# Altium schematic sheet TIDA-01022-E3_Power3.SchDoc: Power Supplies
size 431 x 279 mm; Date: Not shown in title block; ApprovedBy: Not shown in title block; CheckedBy: Not shown in title block; Author: Not shown in title block; CompanyName: Not shown in title block; DrawnBy: Avinash N; Engineer: Not shown in title block; Organization: Not shown in title block; Address1: Not shown in title block; Address2: Not shown in title block; Address3: Not shown in title block; Address4: Not shown in title block; DocumentNumber: 1; Revision: Use project parameter SCH_Rev; SheetNumber: 23; SheetTotal: 26; PageSetup: Record=PageOptions¦CenterHorizontal=True¦CenterVertical=True¦PrintScale=1.00¦XCorrection=1.00¦YCorrection=1.00¦PrintKind=0¦BorderSize=5000000¦LeftOffset=0¦BottomOffset=0¦Orientation=2¦PaperLength=1000¦PaperWidth=1000¦Scale=100¦PaperSource=15¦PrintQuality=600¦MediaType=1¦DitherType=10¦PaperKind=Letter¦PrintScaleMode=1
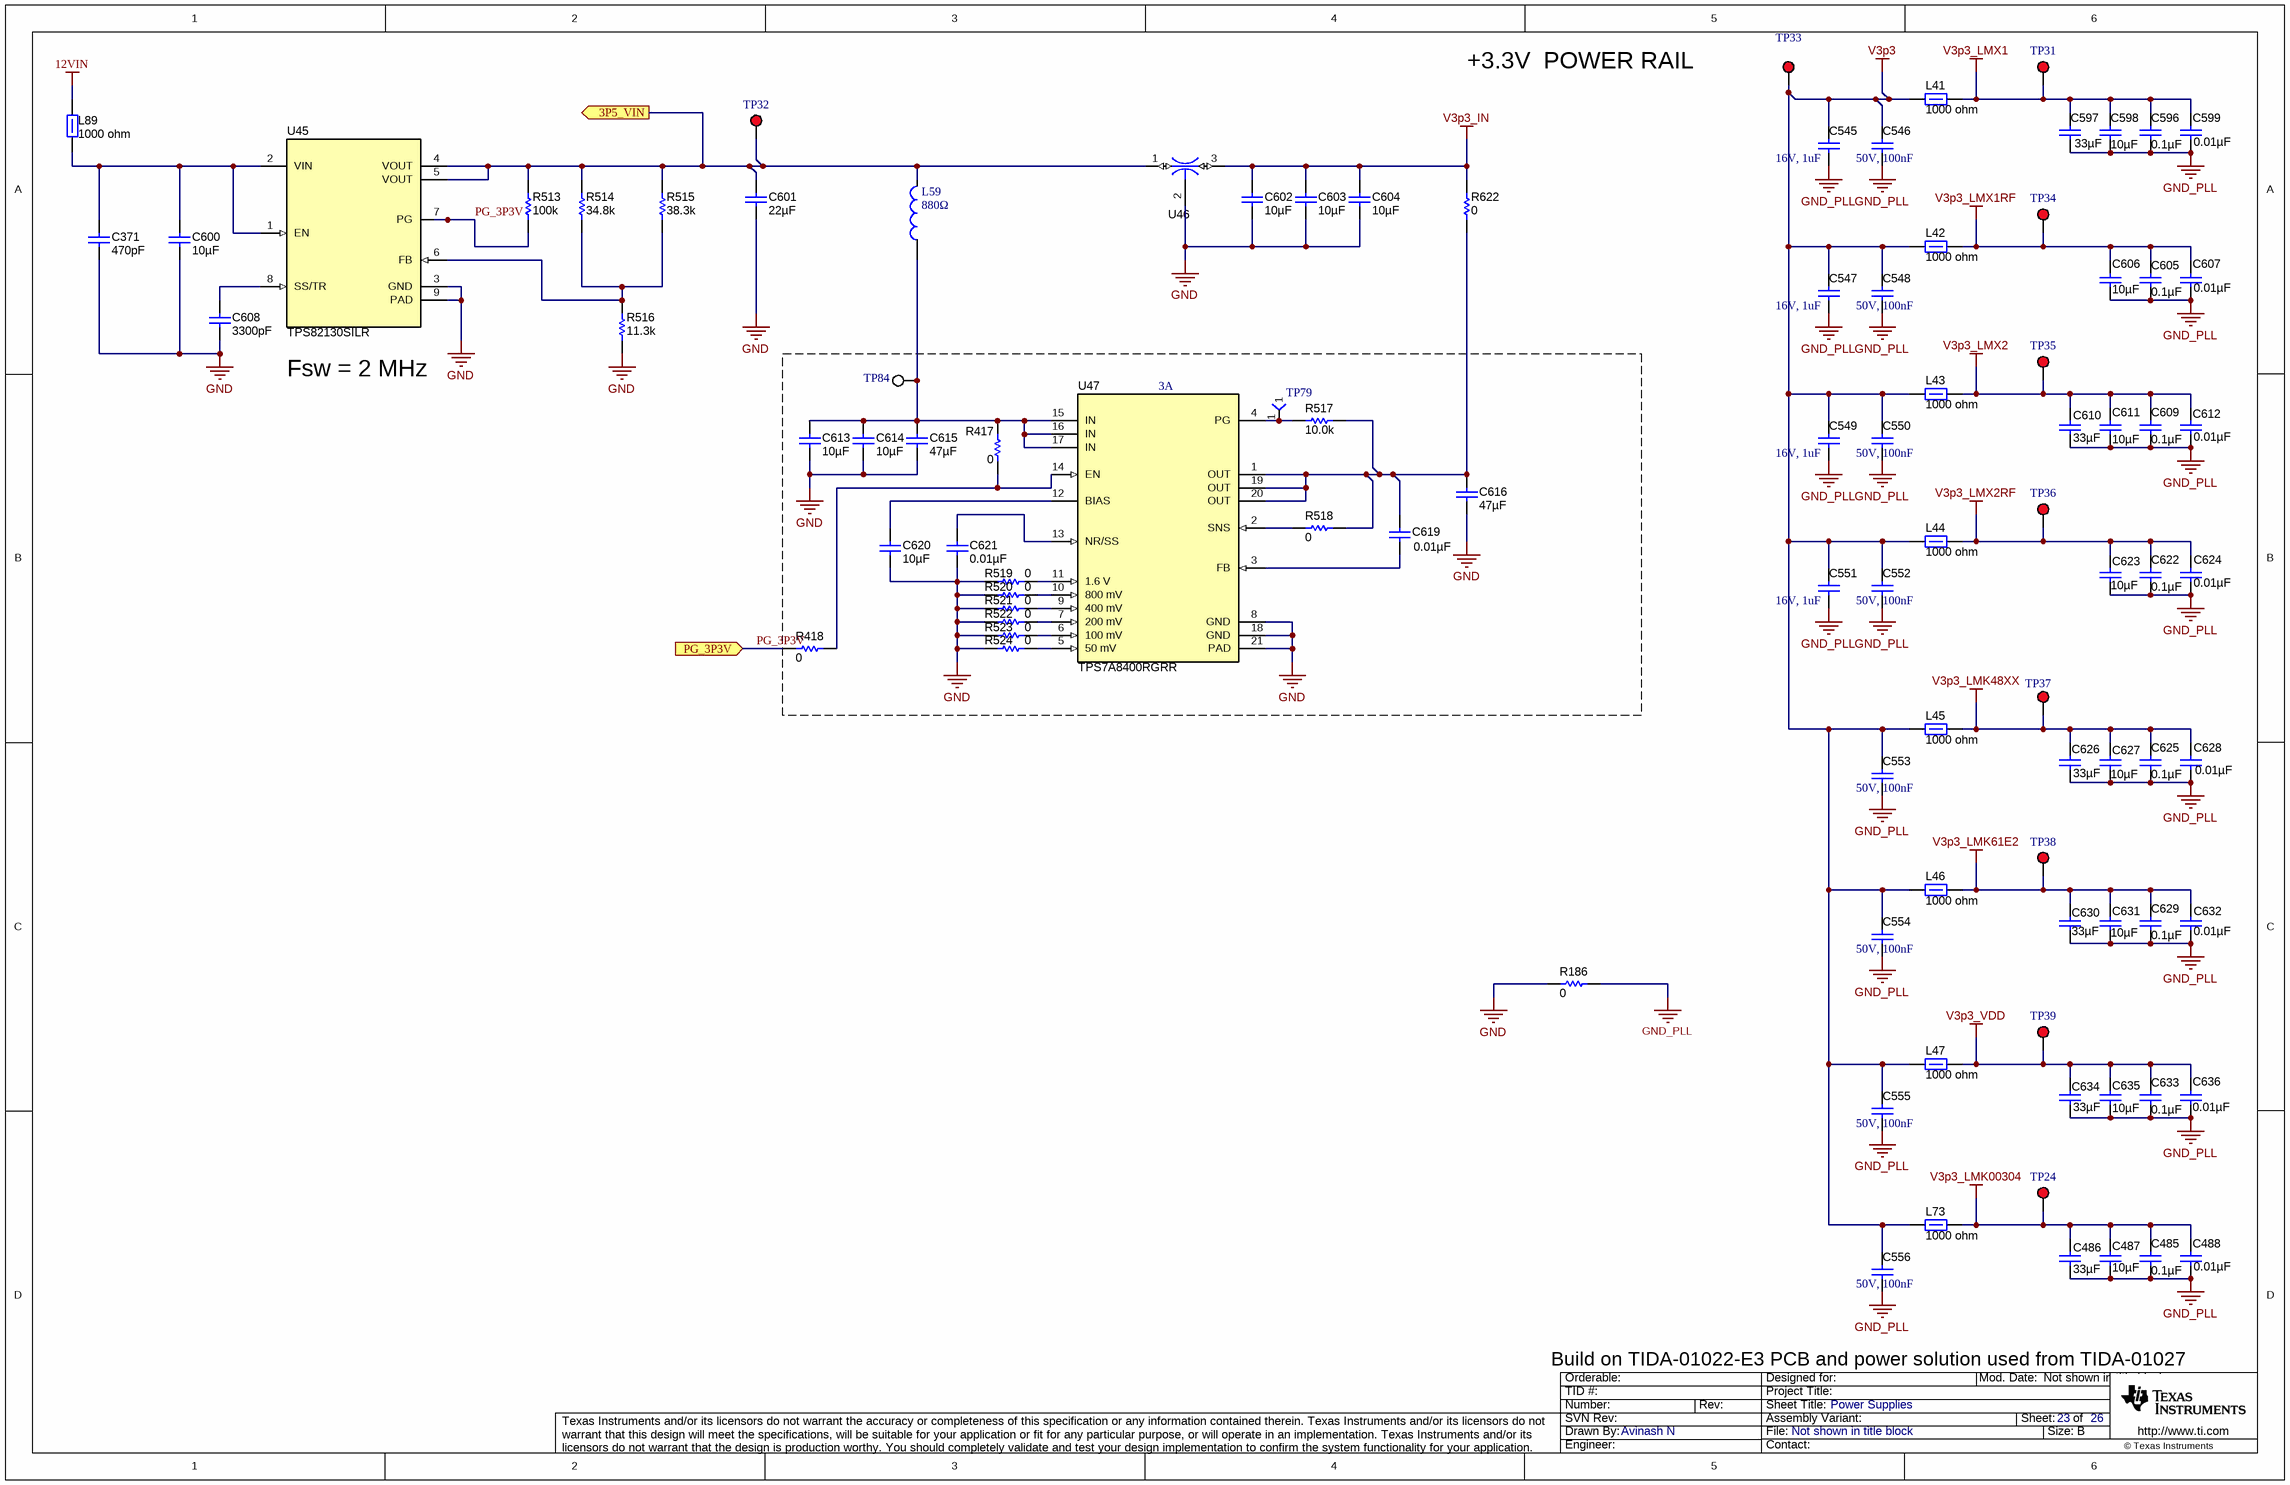
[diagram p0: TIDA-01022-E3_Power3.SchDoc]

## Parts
C371  ValueDisplayed: 470pF  [0402]  (hidden comment: GRM1555C1H471JA01D)
C485  ValueDisplayed: 0.1µF  [0603]  (hidden comment: CGA3E2X7R1H104K080AA)
C486  ValueDisplayed: 33µF  [1206_180]  (hidden comment: C3216X5R1E336M160AC)
C487  ValueDisplayed: 10µF  [1206_190]  (hidden comment: C3216X7R1E106M160AE)
C488  ValueDisplayed: 0.01µF  [0603]  (hidden comment: GCM188R71H103KA37D)
C545  16V, 1uF  [0603_1.6x0.8x0.8mm_Reflow Soldering]
C546  50V, 100nF  [0603_1.6x0.8x0.8mm_Reflow Soldering]
C547  16V, 1uF  [0603_1.6x0.8x0.8mm_Reflow Soldering]
C548  50V, 100nF  [0603_1.6x0.8x0.8mm_Reflow Soldering]
C549  16V, 1uF  [0603_1.6x0.8x0.8mm_Reflow Soldering]
C550  50V, 100nF  [0603_1.6x0.8x0.8mm_Reflow Soldering]
C551  16V, 1uF  [0603_1.6x0.8x0.8mm_Reflow Soldering]
C552  50V, 100nF  [0603_1.6x0.8x0.8mm_Reflow Soldering]
C553  50V, 100nF  [0603_1.6x0.8x0.8mm_Reflow Soldering]
C554  50V, 100nF  [0603_1.6x0.8x0.8mm_Reflow Soldering]
C555  50V, 100nF  [0603_1.6x0.8x0.8mm_Reflow Soldering]
C556  50V, 100nF  [0603_1.6x0.8x0.8mm_Reflow Soldering]
C596  ValueDisplayed: 0.1µF  [0603]  (hidden comment: CGA3E2X7R1H104K080AA)
C597  ValueDisplayed: 33µF  [1206_180]  (hidden comment: C3216X5R1E336M160AC)
C598  ValueDisplayed: 10µF  [1206_190]  (hidden comment: C3216X7R1E106M160AE)
C599  ValueDisplayed: 0.01µF  [0603]  (hidden comment: GCM188R71H103KA37D)
C600  ValueDisplayed: 10µF  [1206_190]  (hidden comment: C3216X7R1E106M160AE)
C601  ValueDisplayed: 22µF  [0805_HV]  (hidden comment: JMK212BJ226MG-T)
C602  ValueDisplayed: 10µF  [1206_190]  (hidden comment: C3216X7R1E106M160AE)
C603  ValueDisplayed: 10µF  [1206_190]  (hidden comment: C3216X7R1E106M160AE)
C604  ValueDisplayed: 10µF  [1206_190]  (hidden comment: C3216X7R1E106M160AE)
C605  ValueDisplayed: 0.1µF  [0603]  (hidden comment: CGA3E2X7R1H104K080AA)
C606  ValueDisplayed: 10µF  [1206_190]  (hidden comment: C3216X7R1E106M160AE)
C607  ValueDisplayed: 0.01µF  [0603]  (hidden comment: GCM188R71H103KA37D)
C608  ValueDisplayed: 3300pF  [0603]  (hidden comment: GRM1885C1H332JA01D)
C609  ValueDisplayed: 0.1µF  [0603]  (hidden comment: CGA3E2X7R1H104K080AA)
C610  ValueDisplayed: 33µF  [1206_180]  (hidden comment: C3216X5R1E336M160AC)
C611  ValueDisplayed: 10µF  [1206_190]  (hidden comment: C3216X7R1E106M160AE)
C612  ValueDisplayed: 0.01µF  [0603]  (hidden comment: GCM188R71H103KA37D)
C613  ValueDisplayed: 10µF  [0805_HV]  (hidden comment: GRM21BR61C106KE15L)
C614  ValueDisplayed: 10µF  [0805_HV]  (hidden comment: GRM21BR61C106KE15L)
C615  ValueDisplayed: 47µF  [0805_HV]  (hidden comment: GRM219R60G476ME44D)
C616  ValueDisplayed: 47µF  [0805_HV]  (hidden comment: GRM219R60G476ME44D)
C619  ValueDisplayed: 0.01µF  [0603]  (hidden comment: GRM188R71H103KA01D)
C620  ValueDisplayed: 10µF  [0805_HV]  (hidden comment: GRM21BR61C106KE15L)
C621  ValueDisplayed: 0.01µF  [0603]  (hidden comment: GRM188R71H103KA01D)
C622  ValueDisplayed: 0.1µF  [0603]  (hidden comment: CGA3E2X7R1H104K080AA)
C623  ValueDisplayed: 10µF  [1206_190]  (hidden comment: C3216X7R1E106M160AE)
C624  ValueDisplayed: 0.01µF  [0603]  (hidden comment: GCM188R71H103KA37D)
C625  ValueDisplayed: 0.1µF  [0603]  (hidden comment: CGA3E2X7R1H104K080AA)
C626  ValueDisplayed: 33µF  [1206_180]  (hidden comment: C3216X5R1E336M160AC)
C627  ValueDisplayed: 10µF  [1206_190]  (hidden comment: C3216X7R1E106M160AE)
C628  ValueDisplayed: 0.01µF  [0603]  (hidden comment: GCM188R71H103KA37D)
C629  ValueDisplayed: 0.1µF  [0603]  (hidden comment: CGA3E2X7R1H104K080AA)
C630  ValueDisplayed: 33µF  [1206_180]  (hidden comment: C3216X5R1E336M160AC)
C631  ValueDisplayed: 10µF  [1206_190]  (hidden comment: C3216X7R1E106M160AE)
C632  ValueDisplayed: 0.01µF  [0603]  (hidden comment: GCM188R71H103KA37D)
C633  ValueDisplayed: 0.1µF  [0603]  (hidden comment: CGA3E2X7R1H104K080AA)
C634  ValueDisplayed: 33µF  [1206_180]  (hidden comment: C3216X5R1E336M160AC)
C635  ValueDisplayed: 10µF  [1206_190]  (hidden comment: C3216X7R1E106M160AE)
C636  ValueDisplayed: 0.01µF  [0603]  (hidden comment: GCM188R71H103KA37D)
L41  ValueDisplayed: 1000 ohm  [1806_HighSpeed]  (hidden comment: BLM41PG102SN1L)
L42  ValueDisplayed: 1000 ohm  [1806_HighSpeed]  (hidden comment: BLM41PG102SN1L)
L43  ValueDisplayed: 1000 ohm  [1806_HighSpeed]  (hidden comment: BLM41PG102SN1L)
L44  ValueDisplayed: 1000 ohm  [1806_HighSpeed]  (hidden comment: BLM41PG102SN1L)
L45  ValueDisplayed: 1000 ohm  [1806_HighSpeed]  (hidden comment: BLM41PG102SN1L)
L46  ValueDisplayed: 1000 ohm  [1806_HighSpeed]  (hidden comment: BLM41PG102SN1L)
L47  ValueDisplayed: 1000 ohm  [1806_HighSpeed]  (hidden comment: BLM41PG102SN1L)
L59  880Ω  [WE-CBF_1812_High Current]
L73  ValueDisplayed: 1000 ohm  [1806_HighSpeed]  (hidden comment: BLM41PG102SN1L)
L89  ValueDisplayed: 1000 ohm  [1806_HighSpeed]  (hidden comment: BLM41PG102SN1L)
R186  ValueDisplayed: 0  [1206]  (hidden comment: CRCW12060000Z0EA)
R417  ValueDisplayed: 0  [0603]  (hidden comment: CRCW06030000Z0EA)
R418  ValueDisplayed: 0  [0603]  (hidden comment: CRCW06030000Z0EA)
R513  ValueDisplayed: 100k  [0402]  (hidden comment: CRCW0402100KFKED)
R514  ValueDisplayed: 34.8k  [0603]  (hidden comment: CRCW060334K8FKEA)
R515  ValueDisplayed: 38.3k  [0402]  (hidden comment: CRCW040238K3FKED)
R516  ValueDisplayed: 11.3k  [0402]  (hidden comment: CRCW040211K3FKED)
R517  ValueDisplayed: 10.0k  [0603]  (hidden comment: CRCW060310K0FKEA)
R518  ValueDisplayed: 0  [0603]  (hidden comment: CRCW06030000Z0EA)
R519  ValueDisplayed: 0  [0402]  (hidden comment: CRCW04020000Z0ED)
R520  ValueDisplayed: 0  [0402]  (hidden comment: CRCW04020000Z0ED)
R521  ValueDisplayed: 0  [0402]  (hidden comment: CRCW04020000Z0ED)
R522  ValueDisplayed: 0  [0402]  (hidden comment: CRCW04020000Z0ED)
R523  ValueDisplayed: 0  [0402]  (hidden comment: CRCW04020000Z0ED)
R524  ValueDisplayed: 0  [0402]  (hidden comment: CRCW04020000Z0ED)
R622  ValueDisplayed: 0  [1206]  (hidden comment: CRCW12060000Z0EA)
TP24  5000  [Keystone5000]  (value not drawn)
TP31  5000  [Keystone5000]  (value not drawn)
TP32  5000  [Keystone5000]  (value not drawn)
TP33  5000  [Keystone5000]  (value not drawn)
TP34  5000  [Keystone5000]  (value not drawn)
TP35  5000  [Keystone5000]  (value not drawn)
TP36  5000  [Keystone5000]  (value not drawn)
TP37  5000  [Keystone5000]  (value not drawn)
TP38  5000  [Keystone5000]  (value not drawn)
TP39  5000  [Keystone5000]  (value not drawn)
TP79  TP-025-SMT  [PROBE_POINT_30PAD]  (value not drawn)
TP84  5015  [Testpoint_Keystone_Miniature]  (value not drawn)
U45  TPS82130SILR  [SIL0008D_SMD]
U46  NFM31PC276B0J3L  [Murata_NFM31P]  (value not drawn)
U47  TPS7A8400RGRR  [RGR0020A]

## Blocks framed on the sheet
3A: C613-C616 C619-C621 R417 R418 R517-R524 TP79 TP84 U47

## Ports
3P5_VIN (out), PG_3P3V (in)

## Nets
12VIN: L89.2
GND: C371.2 C600.2 C601.2 C602.1 C603.1 C604.1 C608.1 C613.2 C614.2 C615.2 C616.2 C620.2 C621.2 R186.1 R516.1 R519.1 R520.1 R521.1 R522.1 R523.1 R524.1 U45.3(GND) U45.9(PAD) U46.2 U47.8(GND) U47.18(GND) U47.21(PAD)
GND_PLL: C485.2 C486.2 C487.1 C488.2 C545.2 C546.1 C547.2 C548.1 C549.2 C550.1 C551.2 C552.1 C553.1 C554.1 C555.1 C556.1 C596.2 C597.2 C598.1 C599.2 C605.2 C606.1 C607.2 C609.2 C610.2 C611.1 C612.2 C622.2 C623.1 C624.2 C625.2 C626.2 C627.1 C628.2 C629.2 C630.2 C631.1 C632.2 C633.2 C634.2 C635.1 C636.2 R186.2
V3p3: C545.1 C546.2 C547.1 C548.2 C549.1 C550.2 C551.1 C552.2 C553.2 C554.2 C555.2 C556.2 L41.1 L42.1 L43.1 L44.1 L45.1 L46.1 L47.1 L73.1 TP33.1
V3p3_IN: C602.2 C603.2 C604.2 R622.2 U46.3
V3p3_LMK48XX: C625.1 C626.1 C627.2 C628.1 L45.2 TP37.1
V3p3_LMK61E2: C629.1 C630.1 C631.2 C632.1 L46.2 TP38.1
V3p3_LMK00304: C485.1 C486.1 C487.2 C488.1 L73.2 TP24.1
V3p3_LMX1: C596.1 C597.1 C598.2 C599.1 L41.2 TP31.1
V3p3_LMX1RF: C605.1 C606.2 C607.1 L42.2 TP34.1
V3p3_LMX2: C609.1 C610.1 C611.2 C612.1 L43.2 TP35.1
V3p3_LMX2RF: C622.1 C623.2 C624.1 L44.2 TP36.1
V3p3_VDD: C633.1 C634.1 C635.2 C636.1 L47.2 TP39.1
3P5_VIN: C601.1 L59.2 R513.2 R514.2 R515.2 TP32.1 U45.4(VOUT) U45.5(VOUT) U46.1 ; port 3P5_VIN
PG_3P3V: R418.2 R513.1 U45.7(PG) ; port PG_3P3V
NetC371_1: C371.1 C600.1 L89.1 U45.1(EN) U45.2(VIN)
NetC608_2: C608.2 U45.8(SS/TR)
NetC613_1: C613.1 C614.1 C615.1 L59.1 R417.1 TP84.1 U47.15(IN) U47.16(IN) U47.17(IN)
NetC616_1: C616.1 C619.1 R517.1 R518.2 R622.1 U47.1(OUT) U47.19(OUT) U47.20(OUT)
NetC619_2: C619.2 U47.3(FB)
NetC620_1: C620.1 U47.12(BIAS)
NetC621_1: C621.1 U47.13(NR/SS)
NetR417_2: R417.2 R418.1 U47.14(EN)
NetR514_1: R514.1 R515.1 R516.2 U45.6(FB)
NetR517_2: R517.2 TP79.1 U47.4(PG)
NetR518_1: R518.1 U47.2(SNS)
NetR519_2: R519.2 U47.11(1.6_V)
NetR520_2: R520.2 U47.10(800_mV)
NetR521_2: R521.2 U47.9(400_mV)
NetR522_2: R522.2 U47.7(200_mV)
NetR523_2: R523.2 U47.6(100_mV)
NetR524_2: R524.2 U47.5(50_mV)

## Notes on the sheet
- +3.3V  POWER RAIL
- Fsw = 2 MHz
- Build on TIDA-01022-E3 PCB and power solution used from TIDA-01027

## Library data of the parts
C371 = GRM1555C1H471JA01D: CAP, CERM, 470 pF, 50 V, +/- 5%, C0G/NP0, 0402; Manufacturer: MuRata; Polarized: N; CompType: Capacitor; Value: 470pF; U/M: EA; Cap_F: 0.00000000047; Tolerance_%: 5; Value1: Unknown; VDC_V: 50; Value2: 50V; TaMin_C: -55; TaMax_C: 125; SizeArea_mm2: 0.5; SizeAreaWB_mm2: 3; SizeX_mm: 1; SizeZ_mm: 0.6; AEC Category: Q200
C485 C596 C605 C609 C622 C625 C629 C633 = CGA3E2X7R1H104K080AA: CAP, CERM, 0.1 µF, 50 V, +/- 10%, X7R, AEC-Q200 Grade 1, 0603; Manufacturer: TDK; Polarized: N; CompType: Capacitor; Value: 0.1uF; U/M: EA; Cap_F: 0.0000001; Tolerance_%: 10; ESR_ohm: 0.0296; Value1: 0.0296 ohm; VDC_V: 50; Value2: 50V; IRMS_A: 0.97199; TaMin_C: -55; TaMax_C: 125; SizeArea_mm2: 1.28; SizeAreaWB_mm2: 4.68; SizeX_mm: 1.6; SizeY_mm: 0.8; SizeZ_mm: 1; AEC Category: Q200; AEC Qualified: Y
C486 C597 C610 C626 C630 C634 = C3216X5R1E336M160AC: CAP, CERM, 33 µF, 25 V, +/- 20%, X5R, 1206; Manufacturer: TDK; Polarized: N; CompType: Capacitor; Value: 33uF; U/M: EA; Cap_F: 0.000033; Tolerance_%: 20; ESR_ohm: 0.002648; Value1: 0.002648 ohm; VDC_V: 25; Value2: 25V; IRMS_A: 4.45864; TaMin_C: -55; TaMax_C: 85; SizeArea_mm2: 5.12; SizeAreaWB_mm2: 10.92; SizeX_mm: 3.2; SizeY_mm: 1.6; SizeZ_mm: 1.8; AEC Category: Q200
C487 C598 C600 C602-C604 C606 C611 C623 C627 C631 C635 = C3216X7R1E106M160AE: CAP, CERM, 10 µF, 25 V, +/- 20%, X7R, 1206_190; Manufacturer: TDK; Polarized: N; CompType: Capacitor; Value: 10uF; U/M: EA; Cap_F: 0.00001; Tolerance_%: 20; Value1: Unknown; VDC_V: 25; Value2: 25V; TaMin_C: -55; TaMax_C: 125; Cap_Case: 1206; SizeArea_mm2: 5.12; SizeAreaWB_mm2: 10.92; SizeX_mm: 3.2; SizeY_mm: 1.6; SizeZ_mm: 1.9; AEC Category: Q200
C488 C599 C607 C612 C624 C628 C632 C636 = GCM188R71H103KA37D: CAP, CERM, 0.01 µF, 50 V, +/- 10%, X7R, AEC-Q200 Grade 1, 0603; Manufacturer: MuRata; Polarized: N; CompType: Capacitor; Value: 0.01uF; U/M: EA; Cap_F: 0.00000001; Tolerance_%: 10; Value1: Unknown; VDC_V: 50; Value2: 50V; TaMin_C: -55; TaMax_C: 125; SizeArea_mm2: 1.28; SizeAreaWB_mm2: 4.68; SizeX_mm: 1.6; SizeY_mm: 0.8; SizeZ_mm: 1; AEC Category: Q200; AEC Qualified: Y
C545 C547 C549 C551 = 885012206052: WCAP-CSGP Ceramic Capacitors, 0603, X7R, 16V, 1uF; Rated Voltage: 16V DC
C546 C548 C550 C552-C556 = 885012206095: WCAP-CSGP Ceramic Capacitors, 0603, X7R, 50V, 100nF; Rated Voltage: 50V DC
C601 = JMK212BJ226MG-T: CAP, CERM, 22 µF, 6.3 V, +/- 20%, X5R, 0805; Manufacturer: Taiyo Yuden; Polarized: N; CompType: Capacitor; Value: 22uF; U/M: EA; Cap_F: 0.000022; Tolerance_%: 20; Value1: Unknown; VDC_V: 6.3; Value2: 6.3V; TaMin_C: -55; TaMax_C: 85; Cap_Case: 0805; SizeArea_mm2: 2.5; SizeAreaWB_mm2: 6.75; SizeX_mm: 2; SizeY_mm: 1.25; SizeZ_mm: 1.45; AEC Category: Q200
C608 = GRM1885C1H332JA01D: CAP, CERM, 3300 pF, 50 V, +/- 5%, C0G/NP0, 0603; Manufacturer: MuRata; Polarized: N; CompType: Capacitor; Value: 3300pF; U/M: EA; Cap_F: 0.0000000033; Tolerance_%: 5; Value1: Unknown; VDC_V: 50; Value2: 50V; TaMin_C: -55; TaMax_C: 125; SizeArea_mm2: 1.28; SizeAreaWB_mm2: 4.68; SizeX_mm: 1.6; SizeY_mm: 0.8; SizeZ_mm: 1; AEC Category: Q200
C613 C614 C620 = GRM21BR61C106KE15L: CAP, CERM, 10 µF, 16 V, +/- 10%, X5R, 0805; Manufacturer: MuRata; Polarized: N; CompType: Capacitor; Value: 10uF; U/M: EA; Cap_F: 0.00001; Tolerance_%: 10; ESR_ohm: 0.008; Value1: 0.008 ohm; VDC_V: 16; Value2: 16V; TaMin_C: -55; TaMax_C: 85; Cap_Case: 0805; SizeArea_mm2: 2.5; SizeAreaWB_mm2: 6.75; SizeX_mm: 2; SizeY_mm: 1.25; SizeZ_mm: 1.45; AEC Category: Q200
C615 C616 = GRM219R60G476ME44D: CAP, CERM, 47 µF, 4 V, +/- 20%, X5R, 0805; Manufacturer: MuRata; Polarized: N; CompType: Capacitor; Value: 47uF; U/M: EA; Cap_F: 0.000047; Tolerance_%: 20; Value1: Unknown; VDC_V: 4; Value2: 4V; TaMin_C: -55; TaMax_C: 85; Cap_Case: 0805; SizeArea_mm2: 2.5; SizeAreaWB_mm2: 6.75; SizeX_mm: 2; SizeY_mm: 1.25; SizeZ_mm: 1.45; AEC Category: Q200
C619 C621 = GRM188R71H103KA01D: CAP, CERM, 0.01 µF, 50 V, +/- 10%, X7R, 0603; Manufacturer: MuRata; Polarized: N; CompType: Capacitor; Value: 0.01uF; U/M: EA; Cap_F: 0.00000001; Tolerance_%: 10; Value1: Unknown; VDC_V: 50; Value2: 50V; TaMin_C: -55; TaMax_C: 125; SizeArea_mm2: 1.28; SizeAreaWB_mm2: 4.68; SizeX_mm: 1.6; SizeY_mm: 0.8; SizeZ_mm: 1; AEC Category: Q200
L41-L47 L73 L89 = BLM41PG102SN1L: Ferrite Bead, 1000 ohm @ 100 MHz, 1.5 A, 1806; Manufacturer: MuRata; Imax_A: 1.5; DCR_ohm: 0.09; Value1: 0.09 ohm; Value2: 1.5A; SizeAreaWB_mm2: 14.3; SizeArea_mm2: 7.2; SizeX_mm: 4.5; SizeY_mm: 1.6; SizeZ_mm: 1.85; ZTyp@100MHz_Ohm: 1000
L59 = WE-CBF, 74279252: WE-CBF SMD EMI Suppression Ferrite Bead, 1812, 880Ω; Type: High Current
R186 = CRCW12060000Z0EA: RES, 0, 5%, 0.25 W, 1206; Manufacturer: Vishay-Dale; CompType: Resistor; Value: 0; Value_Code: 0000; Tolerance_%: 5; Power_W: 0.25; Value2: 0.25W; VDC_V: 200; TempCo: 200 ppm/C; SizeArea_mm2: 5.12; SizeX_mm: 3.2; SizeY_mm: 1.6; SizeZ_mm: 1.35; EIA_Code: E24; U/M: EA; AEC Category: Q200; Green_Lifecycle: Active; Green_REACh: Passed
R417 R418 = CRCW06030000Z0EA: RES, 0, 5%, 0.1 W, 0603; Manufacturer: Vishay-Dale; CompType: Resistor; Value: 0; Value_Code: 0000; Tolerance_%: 5; Power_W: 0.1; Value2: 0.1W; VDC_V: 75; TempCo: 200 ppm/C; SizeArea_mm2: 1.28; SizeX_mm: 1.6; SizeY_mm: 0.8; SizeZ_mm: 1; EIA_Code: E24; U/M: EA; AEC Category: Q200; Green_Lifecycle: Active; Green_REACh: Passed
R513 = CRCW0402100KFKED: RES, 100 k, 1%, 0.063 W, 0402; Manufacturer: Vishay-Dale; CompType: Resistor; Value: 100k; Res_ohm: 100000; Tolerance_%: 1; Power_W: 0.063; Value2: 0.063W; VDC_V: 50; TempCo: 100 ppm/C; SizeArea_mm2: 0.5; SizeZ_mm: 0.6; EIA_Code: E96; U/M: EA; AEC Category: Q200
R514 = CRCW060334K8FKEA: RES, 34.8 k, 1%, 0.1 W, 0603; Manufacturer: Vishay-Dale; CompType: Resistor; Value: 34.8k; Res_ohm: 34800; Value_Code: 34k8; Tolerance_%: 1; Power_W: 0.1; Value2: 0.1W; VDC_V: 75; TempCo: 100 ppm/C; SizeArea_mm2: 1.28; SizeX_mm: 1.6; SizeY_mm: 0.8; EIA_Code: E96; U/M: EA; AEC Category: Q200
R515 = CRCW040238K3FKED: RES, 38.3 k, 1%, 0.063 W, 0402; Manufacturer: Vishay-Dale; CompType: Resistor; Value: 38.3k; Res_ohm: 38300; Value_Code: 38k3; Tolerance_%: 1; Power_W: 0.063; Value2: 0.063W; VDC_V: 50; TempCo: 100 ppm/C; SizeArea_mm2: 0.5; SizeZ_mm: 0.6; EIA_Code: E96; U/M: EA; AEC Category: Q200; Green_Lifecycle: Active; Green_REACh: Passed
R516 = CRCW040211K3FKED: RES, 11.3 k, 1%, 0.063 W, 0402; Manufacturer: Vishay-Dale; CompType: Resistor; Value: 11.3k; Res_ohm: 11300; Value_Code: 11k3; Tolerance_%: 1; Power_W: 0.063; Value2: 0.063W; VDC_V: 50; TempCo: 100 ppm/C; SizeArea_mm2: 0.5; SizeZ_mm: 0.6; EIA_Code: E96; U/M: EA; AEC Category: Q200
R517 = CRCW060310K0FKEA: RES, 10.0 k, 1%, 0.1 W, 0603; Manufacturer: Vishay-Dale; CompType: Resistor; Value: 10.0k; Res_ohm: 10000; Value_Code: 10k0; Tolerance_%: 1; Power_W: 0.1; Value2: 0.1W; VDC_V: 75; TempCo: 100 ppm/C; SizeArea_mm2: 1.28; SizeX_mm: 1.6; SizeY_mm: 0.8; EIA_Code: E96; U/M: EA; AEC Category: Q200
R518 = CRCW06030000Z0EA: RES, 0, 5%, 0.1 W, 0603; Manufacturer: Vishay-Dale; CompType: Resistor; Value: 0; Value_Code: 0000; Tolerance_%: 5; Power_W: 0.1; Value2: 0.1W; VDC_V: 75; TempCo: 200 ppm/C; SizeArea_mm2: 1.28; SizeX_mm: 1.6; SizeY_mm: 0.8; SizeZ_mm: 1; EIA_Code: E24; U/M: EA; AEC Category: Q200
R519-R524 = CRCW04020000Z0ED: RES, 0, 5%, 0.063 W, 0402; Manufacturer: Vishay-Dale; CompType: Resistor; Value: 0; Value_Code: 0000; Tolerance_%: 5; Power_W: 0.063; Value2: 0.063W; VDC_V: 50; TempCo: 200 ppm/C; SizeArea_mm2: 0.5; SizeX_mm: 1; SizeZ_mm: 0.6; EIA_Code: E24; U/M: EA; AEC Category: Q200
R622 = CRCW12060000Z0EA: RES, 0, 5%, 0.25 W, 1206; Manufacturer: Vishay-Dale; CompType: Resistor; Value: 0; Value_Code: 0000; Tolerance_%: 5; Power_W: 0.25; Value2: 0.25W; VDC_V: 200; TempCo: 200 ppm/C; SizeArea_mm2: 5.12; SizeX_mm: 3.2; SizeY_mm: 1.6; SizeZ_mm: 1.35; EIA_Code: E24; U/M: EA; AEC Category: Q200
TP24 TP31-TP39 = 5000: Test Point, Miniature, Red, TH; Manufacturer: Keystone; CompType: Test Point Loop; ContactFinish: Silver; Green_Lifecycle: Active; Green_REACh: Passed
TP79 = TP-025-SMT: Test Point, O.025"; Manufacturer: STD; Value: STD
TP84 = 5015: Test Point, Miniature, SMT; Manufacturer: Keystone; CompType: Test Point Loop; Green_Lifecycle: Active; Green_REACh: Passed
U45 = TPS82130SILR: 3-A 17V Step-down Converter Module with Integrated Inductor, SIL0008D (uSIP-8); Alternate PartNumber: TPS82130SILT; Manufacturer: Texas Instruments; SymbolCreator: Altium; SizeArea_mm2: 12.25; SizeAreaWB_mm2: 20.25; SizeX_mm: 3.5; SizeZ_mm: 1.53; CompType: IC; U/M: EA
U46 = NFM31PC276B0J3L: FILTER LC HIGH FREQ 27uF 1206; Manufacturer: MuRata; SymbolCreator: Altium
U47 = TPS7A8400RGRR: High-Current (3 A), High-Accuracy (1%), Low-Noise (4.4 μVRMS), LDO Voltage Regulator, RGR0020A (VQFN-20); Alternate PartNumber: TPS7A8400RGRT; Manufacturer: Texas Instruments; SymbolCreator: a0411947; SizeArea_mm2: 12.25; SizeAreaWB_mm2: 20.25; SizeX_mm: 3.5; SizeZ_mm: 1; CompType: IC; U/M: EA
